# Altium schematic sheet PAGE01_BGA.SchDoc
size 304 x 177 mm
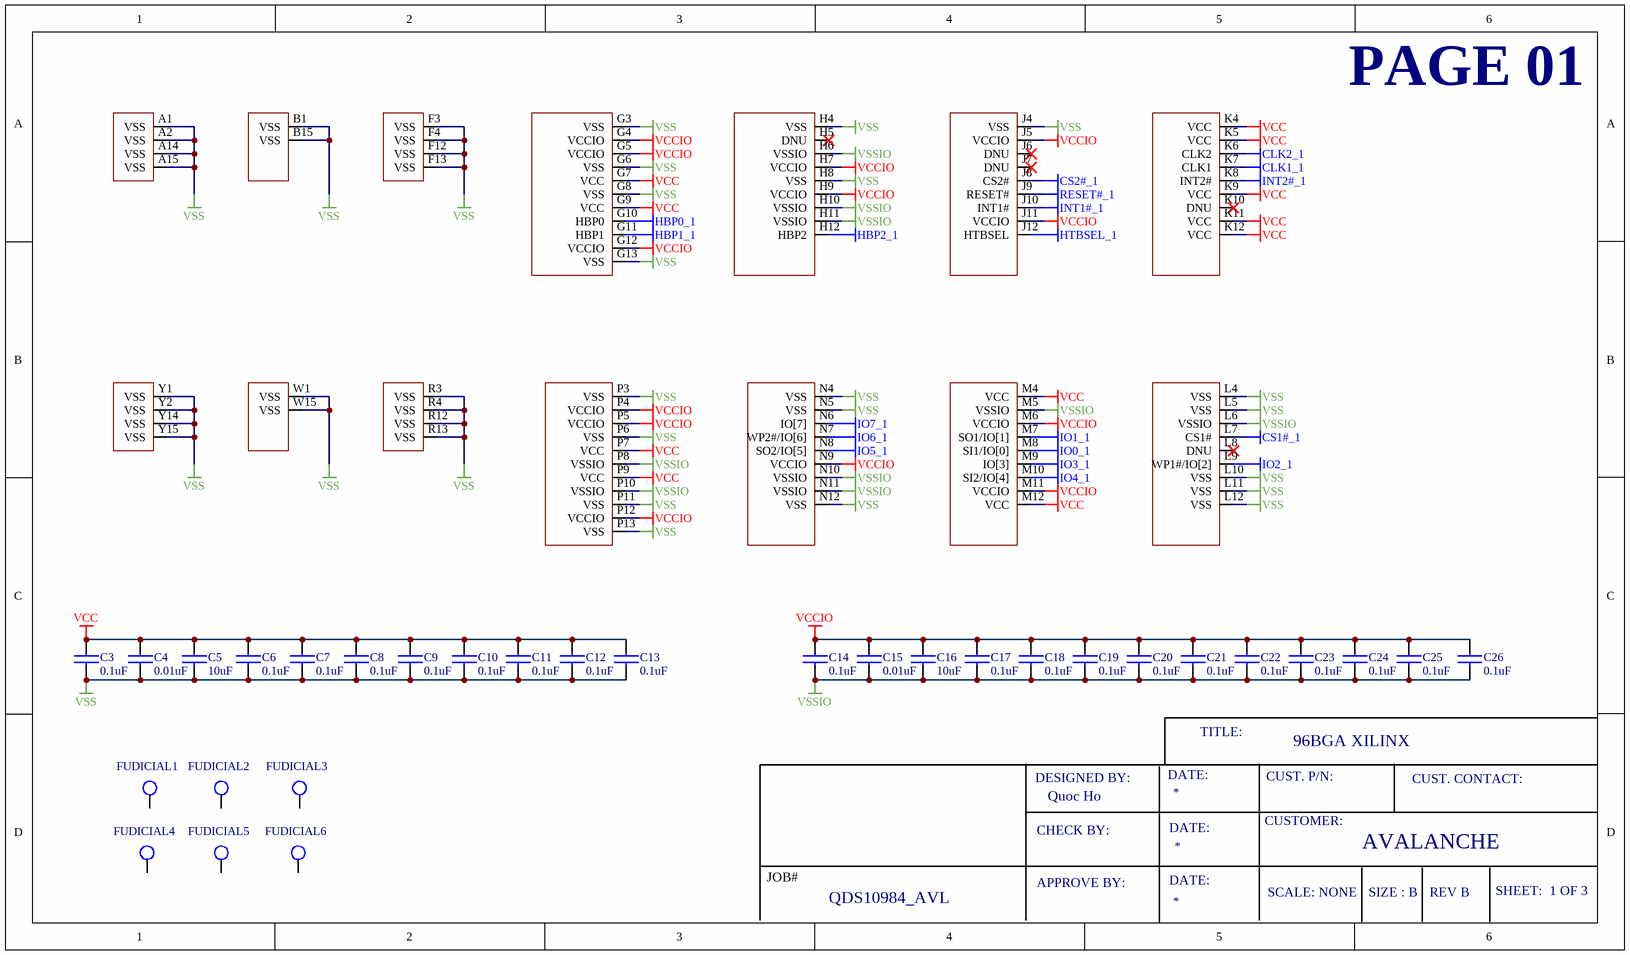
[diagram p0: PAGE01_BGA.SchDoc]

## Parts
C3  0.1uF  [N_0402]
C4  0.01uF  [N_0402]
C5  10uF  [N_0402]
C6  0.1uF  [N_0402]
C7  0.1uF  [N_0402]
C8  0.1uF  [N_0402]
C9  0.1uF  [N_0402]
C10  0.1uF  [N_0402]
C11  0.1uF  [N_0402]
C12  0.1uF  [N_0402]
C13  0.1uF  [N_0402]
C14  0.1uF  [N_0402]
C15  0.01uF  [N_0402]
C16  10uF  [N_0402]
C17  0.1uF  [N_0402]
C18  0.1uF  [N_0402]
C19  0.1uF  [N_0402]
C20  0.1uF  [N_0402]
C21  0.1uF  [N_0402]
C22  0.1uF  [N_0402]
C23  0.1uF  [N_0402]
C24  0.1uF  [N_0402]
C25  0.1uF  [N_0402]
C26  0.1uF  [N_0402]
DUT1  88-BGA  [BGA88]  (value not drawn)
FUDICIAL1  FUDICIAL  [FUDICIAL]  (value not drawn)
FUDICIAL2  FUDICIAL  [FUDICIAL]  (value not drawn)
FUDICIAL3  FUDICIAL  [FUDICIAL]  (value not drawn)
FUDICIAL4  FUDICIAL  [FUDICIAL]  (value not drawn)
FUDICIAL5  FUDICIAL  [FUDICIAL]  (value not drawn)
FUDICIAL6  FUDICIAL  [FUDICIAL]  (value not drawn)

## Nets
CLK1_1: DUT1.K7(CLK1)
CLK2_1: DUT1.K6(CLK2)
CS1#_1: DUT1.L7(CS1#)
CS2#_1: DUT1.J8(CS2#)
HBP0_1: DUT1.G10(HBP0)
HBP1_1: DUT1.G11(HBP1)
HBP2_1: DUT1.H12(HBP2)
HTBSEL_1: DUT1.J12(HTBSEL)
INT1#_1: DUT1.J10(INT1#)
INT2#_1: DUT1.K8(INT2#)
IO0_1: DUT1.M8(SI1/IO[0])
IO1_1: DUT1.M7(SO1/IO[1])
IO2_1: DUT1.L9(WP1#/IO[2])
IO3_1: DUT1.M9(IO[3])
IO4_1: DUT1.M10(SI2/IO[4])
IO5_1: DUT1.N8(SO2/IO[5])
IO6_1: DUT1.N7(WP2#/IO[6])
IO7_1: DUT1.N6(IO[7])
RESET#_1: DUT1.J9(RESET#)
VCC: C3.1 C4.1 C5.1 C6.1 C7.1 C8.1 C9.1 C10.1 C11.1 C12.1 C13.1 DUT1.G7(VCC) DUT1.G9(VCC) DUT1.K4(VCC) DUT1.K5(VCC) DUT1.K9(VCC) DUT1.K11(VCC) DUT1.K12(VCC) DUT1.M4(VCC) DUT1.M12(VCC) DUT1.P7(VCC) DUT1.P9(VCC)
VCCIO: C14.1 C15.1 C16.1 C17.1 C18.1 C19.1 C20.1 C21.1 C22.1 C23.1 C24.1 C25.1 C26.1 DUT1.G4(VCCIO) DUT1.G5(VCCIO) DUT1.G12(VCCIO) DUT1.H7(VCCIO) DUT1.H9(VCCIO) DUT1.J5(VCCIO) DUT1.J11(VCCIO) DUT1.M6(VCCIO) DUT1.M11(VCCIO) DUT1.N9(VCCIO) DUT1.P4(VCCIO) DUT1.P5(VCCIO) DUT1.P12(VCCIO)
VSS: C3.2 C4.2 C5.2 C6.2 C7.2 C8.2 C9.2 C10.2 C11.2 C12.2 C13.2 DUT1.A1(VSS) DUT1.A2(VSS) DUT1.A14(VSS) DUT1.A15(VSS) DUT1.B1(VSS) DUT1.B15(VSS) DUT1.F3(VSS) DUT1.F4(VSS) DUT1.F12(VSS) DUT1.F13(VSS) DUT1.G3(VSS) DUT1.G6(VSS) DUT1.G8(VSS) DUT1.G13(VSS) DUT1.H4(VSS) DUT1.H8(VSS) DUT1.J4(VSS) DUT1.L4(VSS) DUT1.L5(VSS) DUT1.L10(VSS) DUT1.L11(VSS) DUT1.L12(VSS) DUT1.N4(VSS) DUT1.N5(VSS) DUT1.N12(VSS) DUT1.P3(VSS) DUT1.P6(VSS) DUT1.P11(VSS) DUT1.P13(VSS) DUT1.R3(VSS) DUT1.R4(VSS) DUT1.R12(VSS) DUT1.R13(VSS) DUT1.W1(VSS) DUT1.W15(VSS) DUT1.Y1(VSS) DUT1.Y2(VSS) DUT1.Y14(VSS) DUT1.Y15(VSS)
VSSIO: C14.2 C15.2 C16.2 C17.2 C18.2 C19.2 C20.2 C21.2 C22.2 C23.2 C24.2 C25.2 C26.2 DUT1.H6(VSSIO) DUT1.H10(VSSIO) DUT1.H11(VSSIO) DUT1.L6(VSSIO) DUT1.M5(VSSIO) DUT1.N10(VSSIO) DUT1.N11(VSSIO) DUT1.P8(VSSIO) DUT1.P10(VSSIO)

Not connected (* = marked no-connect by the designer): DUT1 H5(DNU)* J6(DNU)* J7(DNU)* K10(DNU)* L8(DNU)*; FUDICIAL1 FUDICIAL; FUDICIAL2 FUDICIAL; FUDICIAL3 FUDICIAL; FUDICIAL4 FUDICIAL; FUDICIAL5 FUDICIAL; FUDICIAL6 FUDICIAL

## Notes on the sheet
- PAGE 01
- TITLE:
- 96BGA XILINX
- DESIGNED BY:
- CHECK BY:
- Quoc Ho
- DATE:
- CUSTOMER:
- CUST. P/N:
- CUST. CONTACT:
- JOB#
- QDS10984_AVL
- APPROVE BY:
- SCALE: NONE
- AVALANCHE
- SIZE : B
- REV B
- SHEET:  1 OF 3

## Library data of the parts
C3 C6-C14 C17-C26 = CAP: CAP CER 0.1UF 16V X7R 0402; Part Number: CL05B104KO5NNNC
C4 C15 = CAP: CAP CER 10000PF 16V X7R 0402; Part Number: CL05B103KO5NNNC
C5 C16 = CAP: CAP CER 10UF 10V X5R 0402; Part Number: CL05A106MP5NUNC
